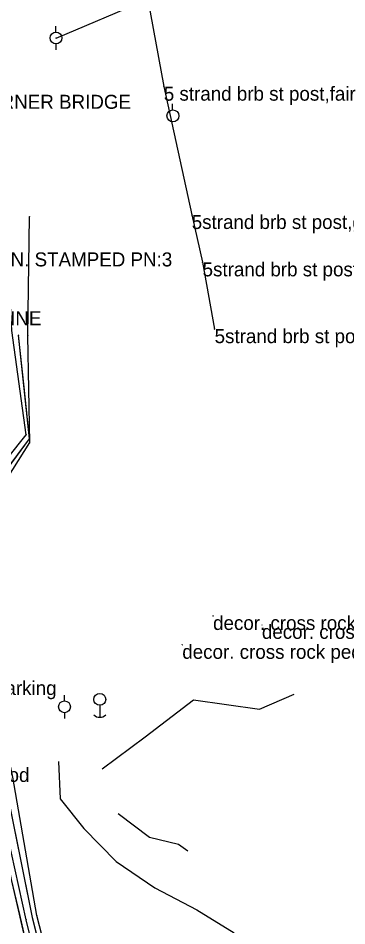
# Model space of a CAD drawing. Extents: x -99999 to 591807, y -99999 to 347168.
# Drawn here: x 591147.4 to 591264.4, y 321509.1 to 321832.8 of the extents above; entities that cross this region are included whole.
import ezdxf

# ---------------------------------------------------------------- set-up
doc = ezdxf.new("R2010")
doc.units = 0
for name, color, linetype in [('S_BREAKLINE', 7, 'Continuous'), ('S_DITCHLINE', 7, 'Continuous'), ('S_ELECTRIC_UTILITIES_ANNOT', 7, 'Continuous'), ('S_FENCE', 7, 'Continuous'), ('S_FENCE_ANNOT', 7, 'Continuous'), ('S_GRD_PT_SYM', 7, 'Continuous'), ('S_MSC_PT_SYM', 7, 'Continuous'), ('S_PRIMARY_CTL_ANNOT', 7, 'Continuous'), ('S_SHOULDER', 7, 'Continuous'), ('S_SURVEY_TEXT_ANNOT', 7, 'Continuous'), ('S_TELEPHONE_UTILITIES', 7, 'Continuous'), ('S_UTILITY_POLE', 7, 'Continuous'), ('S_WALL', 7, 'Continuous')]:
    doc.layers.add(name, color=color, linetype=linetype)

msp = doc.modelspace()

# ---------------------------------------------------------------- linework, layer by layer
at = {"layer": 'S_BREAKLINE'}
for points in [[(591164.29, 321464.11), (591160.94, 321467.78), (591150.17, 321511.25), (591139.68, 321558.73), (591130.5, 321608.9), (591129.11, 321631.45), (591130.93, 321660.22), (591150.25, 321684.23), (591145.13, 321721.39), (591142.84, 321762.86), (591142.09, 321803.81), (591140.61, 321829.22), (591125.84, 321817.1), (591116.3, 321801.5)], [(591164.29, 321464.11), (591165.03, 321469.92), (591153.96, 321512.74), (591145.51, 321562.1), (591135.43, 321608.84), (591136.08, 321633.69), (591139.23, 321662.2), (591151.56, 321681.48), (591150.77, 321719.55), (591151.37, 321761.98)]]:
    msp.add_lwpolyline(points, dxfattribs=at)
at = {"layer": 'S_DITCHLINE'}
for points in [[(591163.02, 321469.77), (591152.44, 321512.03), (591142.76, 321560.48), (591133.42, 321608.63), (591132.57, 321633.73), (591134.12, 321659.38), (591151.43, 321682.76), (591147.49, 321719.73)], [(591163.02, 321469.77), (591157.73, 321490.9), (591152.44, 321512.03), (591147.6, 321536.25), (591142.76, 321560.48), (591138.09, 321584.55), (591133.42, 321608.63), (591132.99, 321621.18), (591132.57, 321633.73), (591133.35, 321646.56), (591134.12, 321659.38), (591142.78, 321671.07), (591151.43, 321682.76), (591149.46, 321701.25), (591147.49, 321719.73)]]:
    msp.add_lwpolyline(points, dxfattribs=at)
at = {"layer": 'S_FENCE'}
for p, q in [((591160.86, 321825.74), (591192.88, 321839.26)), ((591193.61, 321839.59), (591199.24, 321808.4)), ((591199.24, 321808.4), (591209.19, 321762.63)), ((591209.19, 321762.63), (591213.06, 321745.74)), ((591213.06, 321745.74), (591217.34, 321721.91))]:
    msp.add_line(p, q, dxfattribs=at)
for points in [[(591160.86, 321825.74), (591192.88, 321839.26)], [(591193.61, 321839.59), (591199.24, 321808.4)], [(591199.24, 321808.4), (591209.19, 321762.63)], [(591209.19, 321762.63), (591213.06, 321745.74)], [(591213.06, 321745.74), (591217.34, 321721.91)]]:
    msp.add_lwpolyline(points, dxfattribs=at)
at = {"layer": 'S_GRD_PT_SYM'}
for points in [[(591151.37, 321761.98), (591151.32, 321761.98), (591151.37, 321761.98), (591151.37, 321761.93), (591151.37, 321761.98), (591151.42, 321761.98), (591151.37, 321761.98), (591151.37, 321762.03)], [(591147.49, 321719.73), (591147.44, 321719.73), (591147.49, 321719.73), (591147.5, 321719.68), (591147.49, 321719.73), (591147.54, 321719.74), (591147.49, 321719.73), (591147.49, 321719.78)], [(591150.77, 321719.55), (591150.72, 321719.55), (591150.77, 321719.55), (591150.77, 321719.5), (591150.77, 321719.55), (591150.82, 321719.55), (591150.77, 321719.55), (591150.78, 321719.6)], [(591150.25, 321684.23), (591150.2, 321684.22), (591150.25, 321684.23), (591150.26, 321684.18), (591150.25, 321684.23), (591150.3, 321684.24), (591150.25, 321684.23), (591150.24, 321684.28)], [(591151.43, 321682.76), (591151.38, 321682.76), (591151.43, 321682.76), (591151.43, 321682.71), (591151.43, 321682.76), (591151.48, 321682.77), (591151.43, 321682.76), (591151.42, 321682.81)], [(591151.56, 321681.48), (591151.51, 321681.48), (591151.56, 321681.48), (591151.56, 321681.43), (591151.56, 321681.48), (591151.61, 321681.49), (591151.56, 321681.48), (591151.56, 321681.53)], [(591150.17, 321511.25), (591150.12, 321511.24), (591150.17, 321511.25), (591150.18, 321511.2), (591150.17, 321511.25), (591150.22, 321511.26), (591150.17, 321511.25), (591150.16, 321511.3)], [(591152.44, 321512.03), (591152.39, 321512.02), (591152.44, 321512.03), (591152.45, 321511.98), (591152.44, 321512.03), (591152.49, 321512.04), (591152.44, 321512.03), (591152.43, 321512.08)], [(591153.96, 321512.74), (591153.91, 321512.73), (591153.96, 321512.74), (591153.96, 321512.69), (591153.96, 321512.74), (591154.01, 321512.75), (591153.96, 321512.74), (591153.95, 321512.79)]]:
    msp.add_lwpolyline(points, close=True, dxfattribs=at)
at = {"layer": 'S_MSC_PT_SYM'}
for points in [[(591160.86, 321825.74), (591160.86, 321825.79), (591160.86, 321825.74), (591160.81, 321825.74), (591160.86, 321825.74), (591160.86, 321825.69), (591160.86, 321825.74), (591160.91, 321825.74)], [(591199.24, 321808.4), (591199.24, 321808.45), (591199.24, 321808.4), (591199.19, 321808.4), (591199.24, 321808.4), (591199.24, 321808.35), (591199.24, 321808.4), (591199.29, 321808.4)], [(591209.19, 321762.63), (591209.19, 321762.68), (591209.19, 321762.63), (591209.14, 321762.63), (591209.19, 321762.63), (591209.19, 321762.58), (591209.19, 321762.63), (591209.24, 321762.63)], [(591213.06, 321745.74), (591213.06, 321745.79), (591213.06, 321745.74), (591213.01, 321745.74), (591213.06, 321745.74), (591213.06, 321745.69), (591213.06, 321745.74), (591213.11, 321745.74)], [(591217.34, 321721.91), (591217.34, 321721.96), (591217.34, 321721.91), (591217.29, 321721.91), (591217.34, 321721.91), (591217.34, 321721.86), (591217.34, 321721.91), (591217.39, 321721.91)], [(591216.8, 321619.6), (591216.8, 321619.65), (591216.8, 321619.6), (591216.75, 321619.6), (591216.8, 321619.6), (591216.8, 321619.55), (591216.8, 321619.6), (591216.85, 321619.6)], [(591234.19, 321616.44), (591234.19, 321616.49), (591234.19, 321616.44), (591234.14, 321616.44), (591234.19, 321616.44), (591234.19, 321616.39), (591234.19, 321616.44), (591234.24, 321616.44)], [(591205.83, 321609.31), (591205.83, 321609.36), (591205.83, 321609.31), (591205.78, 321609.31), (591205.83, 321609.31), (591205.83, 321609.26), (591205.83, 321609.31), (591205.88, 321609.31)]]:
    msp.add_lwpolyline(points, dxfattribs=at)
at = {"layer": 'S_SHOULDER'}
for points in [[(591099.02, 321821.04), (591101.23, 321815.73), (591103.56, 321785.49), (591108.44, 321745.47), (591114.95, 321696.59), (591120.54, 321658.36), (591129.14, 321608.5), (591136.36, 321567.19), (591144.92, 321525.55), (591156.41, 321475.54), (591170.19, 321423.95), (591174.57, 321415.07), (591182.87, 321407.02), (591194.27, 321399.15), (591205.85, 321394.58)], [(591099.02, 321821.04), (591101.23, 321815.73), (591102.4, 321800.61), (591103.56, 321785.49), (591106, 321765.48), (591108.44, 321745.47), (591111.7, 321721.03), (591114.95, 321696.59), (591117.75, 321677.47), (591120.54, 321658.36), (591122.69, 321645.89), (591124.84, 321633.43), (591126.99, 321620.96), (591129.14, 321608.5), (591132.75, 321587.85), (591136.36, 321567.19), (591140.64, 321546.37), (591144.92, 321525.55), (591147.79, 321513.05), (591150.67, 321500.55)]]:
    msp.add_lwpolyline(points, dxfattribs=at)
at = {"layer": 'S_TELEPHONE_UTILITIES'}
for p, q in [((591160.82, 321827.85), (591160.82, 321829.98)), ((591160.82, 321823.63), (591160.82, 321821.57)), ((591163.85, 321589.27), (591163.85, 321591.4)), ((591163.85, 321585.05), (591163.85, 321582.99))]:
    msp.add_line(p, q, dxfattribs=at)
for centre in [(591160.84, 321825.77), (591163.87, 321587.19)]:
    msp.add_circle(centre, 2.11, dxfattribs=at)
at = {"layer": 'S_UTILITY_POLE'}
for p, q in [((591202.38, 321800.13), (591202.38, 321802.24)), ((591176.45, 321587.67), (591176.45, 321583.43))]:
    msp.add_line(p, q, dxfattribs=at)
for centre in [(591202.5, 321797.99), (591176.44, 321589.85)]:
    msp.add_circle(centre, 2.13, dxfattribs=at)
msp.add_arc((591176.44, 321586.54), 3.09, 226.3972, 313.6028, dxfattribs=at)
at = {"layer": 'S_WALL'}
for points in [[(591177.24, 321565.06), (591192.59, 321576.49), (591209.83, 321589.66), (591233.33, 321586.36), (591245.64, 321591.74)], [(591161.77, 321567.68), (591162.37, 321554.41), (591170.77, 321543.73), (591182.28, 321531.98), (591196.07, 321522.64), (591211.05, 321514.73), (591224.31, 321506.54)], [(591182.99, 321549.16), (591194.13, 321540.68), (591204.44, 321538.18), (591207.86, 321535.82)]]:
    msp.add_lwpolyline(points, dxfattribs=at)

# ---------------------------------------------------------------- texts
at = {"layer": 'S_ELECTRIC_UTILITIES_ANNOT'}
msp.add_text('LOWEST UTILITY LINE', height=5, dxfattribs=at).set_placement((591083.94, 321723.3))
at = {"layer": 'S_FENCE_ANNOT'}
for s, p in [('5 strand brb st post,fair', (591199.24, 321803.4)), ('5strand brb st post,good', (591209.19, 321757.63)), ('5strand brb st post,good', (591213.06, 321740.74)), ('5strand brb st post,good', (591217.34, 321716.91)), ('3ft 2in steel pipe fe,good', (591078.52, 321560.4))]:
    msp.add_text(s, height=5, dxfattribs=at).set_placement(p)
at = {"layer": 'S_PRIMARY_CTL_ANNOT'}
for s, p in [('PD:SQ CUT SW CORNER BRIDGE', (591080.2, 321800.5)), ('PD:ARDOT STD. MON. STAMPED PN:3', (591080.4, 321744.28))]:
    msp.add_text(s, height=5, dxfattribs=at).set_placement(p)
at = {"layer": 'S_SURVEY_TEXT_ANNOT'}
for s, p in [('decor. cross rock pedestal', (591216.8, 321614.6)), ('decor. cross rock pedestal', (591234.19, 321611.44)), ('decor. cross rock pedestal', (591205.83, 321604.31)), ('dw to equipment parking', (591088.2, 321591.38))]:
    msp.add_text(s, height=5, dxfattribs=at).set_placement(p)

doc.saveas('drawing.dxf')
